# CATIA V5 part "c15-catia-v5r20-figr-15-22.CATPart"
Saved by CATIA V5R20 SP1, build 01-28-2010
Part number: Part1
Bounding box of the stored display mesh (mm): x -75 to 76, y -66.397 to 33.603, z 0 to 100
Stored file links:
  D:\v5_r20\psrt_files_downloaded\c15\c15-catia-v5r20-figr-15-22.CATPart
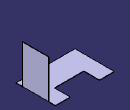
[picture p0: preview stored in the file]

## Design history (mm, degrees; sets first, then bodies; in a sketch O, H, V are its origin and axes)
SheetMetalParameters1: Thickness 1, BendRadius 1, KFactor 0.325257 {= log(min(100,max(20*SheetMetalParameters1.BendRadius,SheetMetalParameters1.Thickness)/SheetMetalParameters1.Thickness))/log(100)/2}, ReliefRadialLength 1, ReliefAxialLength 2, MinimumBendRadius 0
Body1 (main body)
  Sketch1 on xy-plane, origin (0, 0, 0), H (1, 0, 0), V (0, 1, 0)
    line L1 (-37.5, 33.6029) -> (-37.5, -6.3971)
    line L2 (-37.5, -6.3971) -> (37.5, -6.3971)
    line L3 (37.5, -6.3971) -> (37.5, 33.6029)
    line L4 (37.5, 33.6029) -> (75, 33.6029)
    line L5 (75, 33.6029) -> (75, -66.3971)
    line L6 (75, -66.3971) -> (-75, -66.3971)
    line L7 (-75, -66.3971) -> (-75, 33.6029)
    point P8 (-75, 33.6029)
    line L8 (-75, 33.6029) -> (-37.5, 33.6029)
    length L7 = 100
    length L1 = 40
    length L6 = 150
    distance L1 L3 = 75
    vertical: L1 V, L3 V, L5 V, L7 V
    horizontal: L2 H, L4 H, L6 H, L8 H
    coincidence: P8 L4
    symmetry: L7 L5 V, L1 L3 V
  Wall1: Thickness 1, Profile Sketch1
  d_NewWallOnEdge1: NewWallOnEdge_Edge edge [face of Wall1 | face of Wall1], NewWallOnEdge_Length 100, NewWallOnEdge_HeightLimitOffset 0, NewWallOnEdge_WidthOffset1 -16, NewWallOnEdge_WidthOffset2 -17, NewWallOnEdge_Angle 90, NewWallOnEdge_BendRadiusValue 1 {= SheetMetalParameters1.BendRadius}, NewWallOnEdge_BendTable SheetMetalParameters1, KFacteur 0.325257 {= log(min(100,max(20*d_NewWallOnEdge1.Radius,SheetMetalParameters1.Thickness)/SheetMetalParameters1.Thickness))/log(100)/2}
